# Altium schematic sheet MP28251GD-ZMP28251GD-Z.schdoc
size 127 x 101 mm
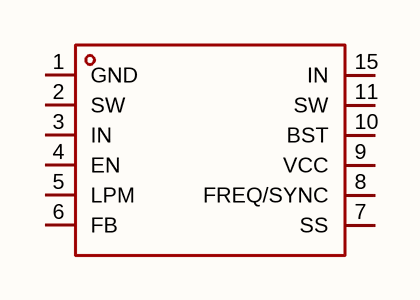
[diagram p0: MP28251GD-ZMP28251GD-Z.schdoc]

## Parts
U?  mp28251gd-z  [QFN-14_L3.0-W2.0-P0.50-TL-EP]  (value not drawn)

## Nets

Not connected (* = marked no-connect by the designer): U? 1(GND) 2(SW) 3(IN) 4(EN) 5(LPM) 6(FB) 7(SS) 8(FREQ/SYNC) 9(VCC) 10(BST) 11(SW) 15(IN)

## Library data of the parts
U? = mp28251gd-z: 功能类型:降压型;工作电压:4.75V~20V;输出电压:800mV~17V;输出电流:4A;输出类型:可调;; Manufacturer: MPS(芯源); AddInBom: yes; ModelId: 94e6ffb66efa4c49a9d2a8343dfc4919; ModelTransform: 79.527,118.8974,0,0,0,0,0,6.968,0; Function: 降压型; Output Current: 4A; Frequency - Switching: 500kHz; Synchronous Rectifier: 是; Number of Outputs: 1; Topology: 降压式; Quiescent Current: 1mA; Switch tube (built-in/external): 内置; Output Type: 可调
